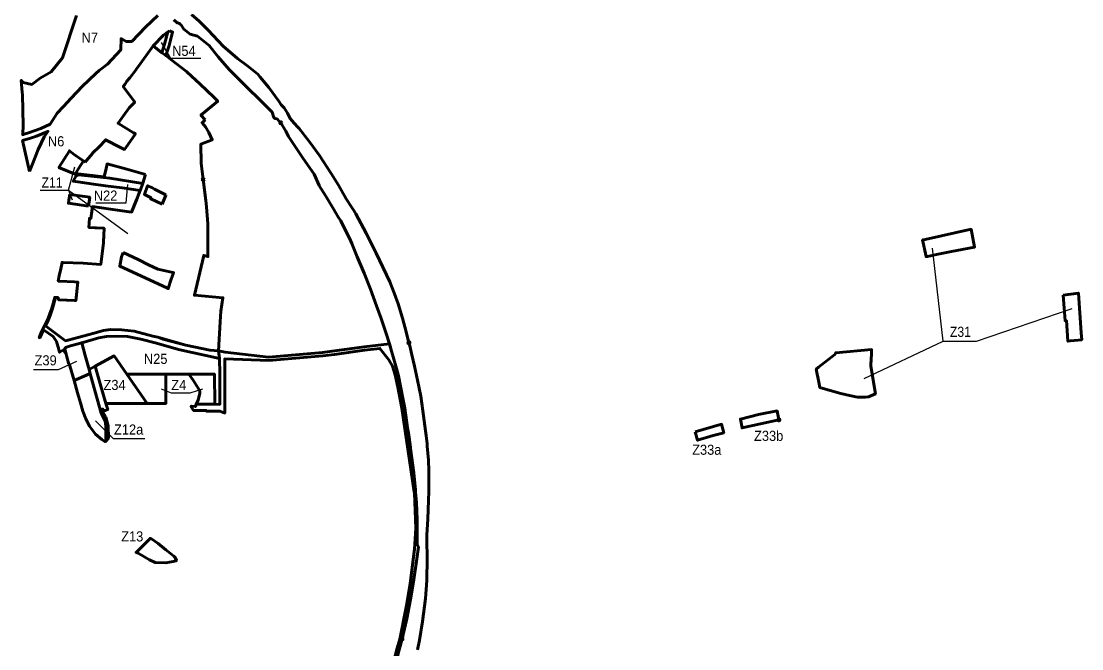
# Model space of a CAD drawing. Extents: x -650277 to -643420, y -1073980 to -1066720.
# Drawn here: x -645938 to -643420, y -1070698 to -1069207 of the extents above; entities that cross this region are included whole.
import ezdxf

# ---------------------------------------------------------------- set-up
doc = ezdxf.new("R2010")
doc.units = 0
doc.header["$LTSCALE"] = 9.6
doc.header["$PDMODE"] = 32
doc.header["$PDSIZE"] = 4.8
for name, color, linetype, lineweight in [('1', 7, 'Continuous', 60), ('11', 7, 'Continuous', 60), ('15', 7, 'Continuous', 60), ('3', 7, 'Continuous', 60), ('40', 7, 'Continuous', 60), ('42', 7, 'Continuous', 60), ('5', 7, 'Continuous', 60), ('60', 7, 'Continuous', 60), ('63', 7, 'Continuous', 25), ('7', 7, 'Continuous', 60), ('8', 7, 'Continuous', 60)]:
    doc.layers.add(name, color=color, linetype=linetype, lineweight=lineweight)

msp = doc.modelspace()

# ---------------------------------------------------------------- linework, layer by layer
at = {"layer": '1'}
for p, q in [((-645623.75, -1069825.97), (-645590.964, -1069841.09)), ((-645726.542, -1069939.398), (-645742.967, -1069941.862))]:
    msp.add_line(p, q, dxfattribs=at)
for points in [[(-645668.722, -1069398.75), (-645696.19, -1069362.01), (-645692.38, -1069356.67), (-645690.81, -1069354.28), (-645687.22, -1069349), (-645680.8, -1069341.08), (-645667, -1069324.06), (-645664.89, -1069320.2), (-645658.9, -1069312.83), (-645625.11, -1069265.42), (-645604.114, -1069281.49), (-645594.94, -1069288.511)], [(-645594.94, -1069288.511), (-645583.13, -1069297.55), (-645546.19, -1069325.81), (-645544.26, -1069327.35), (-645513.41, -1069356.18), (-645480.72, -1069386.96), (-645471.738, -1069397.026), (-645511.464, -1069429.794), (-645501.878, -1069440.838)], [(-645707.04, -1069449.546), (-645708.48, -1069448.63), (-645696.45, -1069432.21), (-645682.28, -1069412.88), (-645678.06, -1069408.54), (-645668.61, -1069398.9), (-645668.722, -1069398.75)], [(-645501.878, -1069440.838), (-645508.994, -1069447.955), (-645501, -1069458), (-645493, -1069471), (-645484.783, -1069488.256), (-645512, -1069499), (-645511, -1069544), (-645506, -1069583)], [(-645786.388, -1069541.673), (-645779.376, -1069532.962), (-645778.754, -1069532.198), (-645769.369, -1069520.672), (-645768.995, -1069520.305), (-645752.715, -1069504.328), (-645738.986, -1069489.868), (-645737.897, -1069488.534), (-645702.82, -1069506.64), (-645692.87, -1069511.229), (-645690.84, -1069508.32), (-645667.31, -1069474.6), (-645671.75, -1069471.99), (-645707.04, -1069449.546)], [(-645836.44, -1069534.5), (-645824.05, -1069514.34), (-645811.75, -1069523.81), (-645808.1, -1069526.61), (-645799.07, -1069532.8), (-645790.62, -1069538.59), (-645786.388, -1069541.673)], [(-645810.08, -1069570.39), (-645848.78, -1069553.91), (-645836.44, -1069534.5)], [(-645643.16, -1069570.6), (-645687.29, -1069558.04), (-645734.5, -1069545.89), (-645736.8, -1069556.91), (-645741.14, -1069576.19), (-645769.04, -1069573), (-645803.513, -1069569.263), (-645810.08, -1069570.39)], [(-645676.34, -1069660.28), (-645670.23, -1069644.67), (-645664.19, -1069629.24), (-645657.52, -1069612.2), (-645656.15, -1069608.71), (-645649.91, -1069592.39), (-645648.68, -1069589.06), (-645644.56, -1069575.61), (-645643.16, -1069570.6)], [(-645594.58, -1069619.56), (-645621.56, -1069605.68), (-645626.95, -1069602.91), (-645638.203, -1069597.8), (-645645.715, -1069618.085), (-645629.78, -1069626.03), (-645630.93, -1069628.84), (-645603.7, -1069641.75)], [(-645506, -1069583), (-645500.137, -1069632.833), (-645500.137, -1069632.833)], [(-645849.79, -1069868.4), (-645811.848, -1069870.577), (-645808.84, -1069870.75), (-645804.28, -1069826.76), (-645812.18, -1069826.3), (-645847.62, -1069824.26), (-645850.63, -1069824.09), (-645848.35, -1069812.09), (-645844.57, -1069795.07), (-645841.41, -1069779.76), (-645839.658, -1069779.835), (-645791.2, -1069781.92), (-645749.48, -1069784.61), (-645743.36, -1069733.7), (-645741.43, -1069698.68), (-645777.62, -1069696.85), (-645776.45, -1069675.26), (-645773.02, -1069675.47), (-645769.264, -1069647.213), (-645726.57, -1069653.22), (-645676.34, -1069660.28), (-645664.19, -1069629.24), (-645656.15, -1069608.71)], [(-645823.082, -1069618.279), (-645823.13, -1069618.452), (-645825.295, -1069632.053), (-645826.133, -1069638.843), (-645826.151, -1069639.057), (-645778.45, -1069645.92)], [(-645778.45, -1069645.92), (-645775.46, -1069625.13), (-645823.082, -1069618.279)], [(-645603.7, -1069641.75), (-645594.818, -1069620.139), (-645594.58, -1069619.56)], [(-645839.721, -1069780.247), (-645839.658, -1069779.835), (-645791.2, -1069781.92), (-645749.48, -1069784.61), (-645743.36, -1069733.7), (-645743.01, -1069730.72), (-645741.43, -1069698.68), (-645763.24, -1069697.58), (-645777.62, -1069696.85), (-645776.45, -1069675.26), (-645773.02, -1069675.47), (-645769.36, -1069648), (-645769.264, -1069647.213), (-645726.57, -1069653.22), (-645676.34, -1069660.28)], [(-645500.137, -1069632.833), (-645498, -1069648), (-645495, -1069688), (-645495, -1069744), (-645495, -1069766), (-645504.976, -1069763.332), (-645527, -1069858), (-645459.312, -1069864.01), (-645464.288, -1069895.362), (-645465.756, -1069921.035), (-645469.701, -1069990.011)], [(-645696.517, -1069756.039), (-645700.028, -1069766.286), (-645704.355, -1069788.786), (-645623.75, -1069825.97)], [(-645578.134, -1069803.73), (-645613.84, -1069795.78), (-645635.79, -1069785.23), (-645660.57, -1069773.31), (-645696.517, -1069756.039)], [(-645804.185, -1069825.84), (-645804.28, -1069826.76), (-645812.18, -1069826.3), (-645847.62, -1069824.26), (-645850.63, -1069824.09), (-645848.35, -1069812.09), (-645844.57, -1069795.07), (-645841.41, -1069779.76), (-645839.658, -1069779.835), (-645839.721, -1069780.247)], [(-645742.967, -1069941.862), (-645768.424, -1069948.431), (-645833, -1069966), (-645880.431, -1069930.3), (-645874.219, -1069917.496), (-645869.262, -1069905.935), (-645863.95, -1069889.468), (-645857.289, -1069863.338), (-645857.204, -1069862.954), (-645850.92, -1069863.41), (-645849.79, -1069868.4), (-645808.84, -1069870.75), (-645808.28, -1069865.39), (-645804.185, -1069825.84)], [(-645590.964, -1069841.09), (-645589.23, -1069841.89), (-645582.31, -1069820.05), (-645577.52, -1069807.26), (-645576.34, -1069804.13), (-645578.134, -1069803.73)], [(-645469.701, -1069990.011), (-645490.814, -1069988.074), (-645547.4, -1069976.382), (-645614.072, -1069957.797), (-645625.979, -1069954.92), (-645670.325, -1069943.002), (-645699.889, -1069939.714), (-645726.542, -1069939.398)], [(-645772.853, -1070049.868), (-645774.423, -1070044.167), (-645783.063, -1070047.855), (-645812.76, -1070060.53)], [(-645737.756, -1070204.389), (-645737.624, -1070169.544), (-645738.79, -1070156.281), (-645748.62, -1070137.889), (-645772.853, -1070049.868)], [(-645812.76, -1070060.53), (-645804.52, -1070089.63), (-645797.66, -1070113.88), (-645791.72, -1070133.09), (-645784.83, -1070151.9), (-645784.83, -1070151.9)], [(-645784.83, -1070151.9), (-645776.26, -1070168.94), (-645761.78, -1070188.29), (-645746.73, -1070201.04), (-645739.12, -1070205.9), (-645737.756, -1070204.389)]]:
    msp.add_lwpolyline(points, dxfattribs=at)
for points in [[(-645836.44, -1069534.5), (-645848.78, -1069553.91), (-645810.08, -1069570.39), (-645803.07, -1069558.62), (-645790.62, -1069538.59), (-645799.07, -1069532.8), (-645808.1, -1069526.61), (-645811.75, -1069523.81), (-645824.05, -1069514.34)], [(-645639.638, -1070114.895), (-645594.733, -1070114.868), (-645595.2, -1070045.403), (-645687.31, -1070045.724)], [(-645522.587, -1070116.952), (-645478.664, -1070117.114), (-645479.429, -1070045.409), (-645540.433, -1070045.752), (-645530.3, -1070060.08), (-645514.49, -1070085.4), (-645514.56, -1070090.91), (-645514.61, -1070094.35), (-645517.02, -1070103.08), (-645518.35, -1070106.87), (-645521.73, -1070114.83)], [(-645594.769, -1070494.065), (-645577.47, -1070490.3), (-645571.13, -1070488.89), (-645569.97, -1070488.3), (-645572.86, -1070481.41), (-645575.7, -1070477.77), (-645591.49, -1070465.19), (-645594.62, -1070462.7), (-645612.77, -1070447.82), (-645631.63, -1070435.3), (-645636.42, -1070439.93), (-645648.9, -1070452.38), (-645665.6, -1070469.04), (-645660.29, -1070471.12), (-645643.4, -1070481.02), (-645633.35, -1070486.91), (-645620.22, -1070493)]]:
    msp.add_lwpolyline(points, close=True, dxfattribs=at)
msp.add_point((-645506, -1069583), dxfattribs=at)
at = {"layer": '11'}
msp.add_lwpolyline([(-645639.638, -1070114.895), (-645687.31, -1070045.724), (-645717.36, -1070002.12), (-645762.868, -1070026.606), (-645757.215, -1070045.97), (-645737.075, -1070114.955)], close=True, dxfattribs=at)
at = {"layer": '15'}
for points in [[(-645586.39, -1069229.32), (-645589.844, -1069231.908), (-645597.738, -1069261.522), (-645604.114, -1069281.49), (-645594.94, -1069288.511), (-645587.298, -1069264.578), (-645578.713, -1069232.375)], [(-645735.532, -1069956.306), (-645712.222, -1069954.725), (-645686.147, -1069956.306), (-645654.145, -1069962.232), (-645617.403, -1069971.714), (-645565.133, -1069986.508), (-645467.472, -1070008.38), (-645469.701, -1069990.011), (-645490.814, -1069988.074), (-645547.4, -1069976.382), (-645601.753, -1069962.317), (-645614.072, -1069957.797), (-645625.979, -1069954.92), (-645670.325, -1069943.002), (-645699.889, -1069939.714), (-645726.542, -1069939.398), (-645742.967, -1069941.862), (-645768.424, -1069948.431), (-645806, -1069959), (-645833, -1069966), (-645880.431, -1069930.3), (-645874.219, -1069917.496), (-645869.262, -1069905.935), (-645863.95, -1069889.468), (-645857.289, -1069863.338), (-645857.204, -1069862.954), (-645858.78, -1069862.84), (-645865.78, -1069888.76), (-645870.89, -1069903.5), (-645876.15, -1069916.47), (-645892.09, -1069947.98), (-645895.66, -1069958.42), (-645894.25, -1069958.7), (-645885.422, -1069940.184), (-645862.782, -1069955.809), (-645854.81, -1069967.927), (-645849.1, -1069986.42), (-645847.135, -1069993.337), (-645836.64, -1069987.18), (-645834.65, -1069994.21), (-645833.32, -1069991.86), (-645835, -1069985), (-645833, -1069982), (-645821, -1069978), (-645794.679, -1069970.596), (-645753.706, -1069959.071)]]:
    msp.add_lwpolyline(points, close=True, dxfattribs=at)
for points in [[(-645061.76, -1069981.21), (-645064.052, -1069973.429), (-645124.233, -1069980.695), (-645222.809, -1069993.701), (-645350.784, -1070005.227), (-645453.852, -1069992.968), (-645469.701, -1069990.011), (-645467.472, -1070008.38), (-645467.068, -1070044.959), (-645466.96, -1070117.157), (-645478.664, -1070117.114), (-645522.587, -1070116.952), (-645524.82, -1070122.48), (-645534.63, -1070121.09), (-645534.7, -1070122.95), (-645529.17, -1070131.4), (-645499.276, -1070131.652), (-645499.142, -1070133.293), (-645466.862, -1070133.219), (-645454.881, -1070137.836), (-645455.073, -1070009.111), (-645350.591, -1070013.242), (-645221.99, -1070001.66), (-645194.003, -1069998.417), (-645123.206, -1069988.629), (-645086.484, -1069984.195), (-645065.235, -1070011.695)], [(-645033.53, -1070674.55), (-645022.64, -1070626.93), (-645014.07, -1070580.72), (-645006.44, -1070538.78), (-644998.92, -1070484.58), (-644995.14, -1070455.72), (-644998.17, -1070450.59), (-644998.25, -1070430.5), (-644997.87, -1070391.16), (-644999.47, -1070349.63), (-645001.64, -1070326.4), (-645001.81, -1070324.58), (-645002.308, -1070319.268), (-645005.98, -1070280.14), (-645013.51, -1070222.04), (-645013.77, -1070220.04), (-645016.92, -1070196.32), (-645018.56, -1070184.92), (-645021.14, -1070173.07), (-645027.49, -1070126.56), (-645032.21, -1070102.73), (-645042.27, -1070049.23), (-645047.28, -1070031.83), (-645054.73, -1070004.56), (-645060.612, -1069985.022), (-645061.76, -1069981.21)], [(-645757.215, -1070045.97), (-645762.868, -1070026.606), (-645777.143, -1070034.287), (-645772.853, -1070049.868), (-645748.62, -1070137.889)], [(-645065.235, -1070011.695), (-645056.555, -1070026.163), (-645050.293, -1070047.035), (-645043.92, -1070076.344), (-645034.122, -1070126.616), (-645004.791, -1070324.889), (-645004.523, -1070326.697)], [(-645737.63, -1070147.39), (-645747.67, -1070129.14), (-645745.29, -1070127.83), (-645744.73, -1070129), (-645743.87, -1070130.15), (-645742.67, -1070131.07), (-645741.83, -1070131.53), (-645740.89, -1070131.8), (-645739.41, -1070131.93), (-645738.41, -1070131.78), (-645737.48, -1070131.45), (-645734.77, -1070130.18), (-645732.91, -1070129.5), (-645737.075, -1070114.955), (-645757.215, -1070045.97)], [(-645748.62, -1070137.889), (-645738.79, -1070156.281), (-645737.624, -1070169.544), (-645737.756, -1070204.389)], [(-645737.756, -1070204.389), (-645731.3, -1070197.24), (-645731.94, -1070167.87), (-645737.63, -1070147.39)], [(-645004.523, -1070326.697), (-645004.434, -1070327.302), (-645001.312, -1070412.099), (-645004.327, -1070461.264), (-645014.277, -1070543.11), (-645023.048, -1070595.033), (-645039.574, -1070675.065)], [(-645039.574, -1070675.065), (-645045.493, -1070696.321), (-645059.308, -1070747.712), (-645059.403, -1070749.195), (-645053.21, -1070749.75), (-645052.4, -1070746.427), (-645046.63, -1070722.77), (-645041, -1070700.44), (-645033.53, -1070674.55)]]:
    msp.add_lwpolyline(points, dxfattribs=at)
msp.add_point((-645033.53, -1070674.55), dxfattribs=at)
at = {"layer": '3'}
for points in [[(-643791.88, -1069725.25), (-643797.75, -1069726.51), (-643789.3, -1069766.05), (-643786.35, -1069765.46), (-643764.94, -1069761.27), (-643729.34, -1069754.3), (-643674.3, -1069743.53), (-643682.61, -1069701.16)], [(-643463.51, -1069857.44), (-643459.13, -1069918.47), (-643456.14, -1069918.26), (-643452.63, -1069967.09), (-643446.63, -1069966), (-643419.62, -1069963.66), (-643420.79, -1069947.35), (-643427.6, -1069852.59)], [(-643920.84, -1070026.46), (-643920.29, -1070017.73), (-643920.16, -1070015.69), (-643918.69, -1069992.23), (-643918.88, -1069986.82), (-644004.06, -1069994.59), (-644005.92, -1069998.62), (-644044.7, -1070029.04), (-644050.12, -1070033.64), (-644044.18, -1070064.43), (-644041.71, -1070077.29), (-644022.77, -1070082.66), (-643991.99, -1070091.37), (-643971.03, -1070095.79), (-643951.99, -1070100.35), (-643933.96, -1070100.18), (-643926.33, -1070099.5), (-643909.87, -1070091.95)]]:
    msp.add_lwpolyline(points, close=True, dxfattribs=at)
for points in [[(-645794.679, -1069970.596), (-645821, -1069978), (-645833, -1069982), (-645835, -1069985), (-645833.32, -1069991.86)], [(-645777.143, -1070034.287), (-645786.238, -1070001.251), (-645794.679, -1069970.596)], [(-645833.32, -1069991.86), (-645828.9, -1070007.76), (-645825.08, -1070021.52)], [(-645825.08, -1070021.52), (-645823.76, -1070021.67), (-645822.549, -1070025.948), (-645812.76, -1070060.53), (-645783.063, -1070047.855), (-645774.423, -1070044.167), (-645777.143, -1070034.287)]]:
    msp.add_lwpolyline(points, dxfattribs=at)
at = {"layer": '40'}
for points in [[(-645698.83, -1069602.85), (-645656.15, -1069608.71), (-645649.91, -1069592.39), (-645727.71, -1069579.61), (-645803.33, -1069571.62), (-645808.18, -1069573.7), (-645814.82, -1069586.81), (-645777.26, -1069592.07), (-645772.58, -1069592.73), (-645738.13, -1069597.46)], [(-645595.2, -1070045.403), (-645479.429, -1070045.409), (-645478.664, -1070117.114), (-645466.96, -1070117.157), (-645467.068, -1070044.959), (-645467.472, -1070008.38), (-645565.133, -1069986.508), (-645617.403, -1069971.714), (-645654.145, -1069962.232), (-645686.147, -1069956.306), (-645712.222, -1069954.725), (-645735.532, -1069956.306), (-645753.706, -1069959.071), (-645794.679, -1069970.596), (-645786.238, -1070001.251), (-645777.143, -1070034.287), (-645762.868, -1070026.606), (-645717.36, -1070002.12), (-645687.31, -1070045.724)]]:
    msp.add_lwpolyline(points, close=True, dxfattribs=at)
at = {"layer": '42'}
msp.add_lwpolyline([(-645604.114, -1069281.49), (-645597.738, -1069261.522), (-645589.844, -1069231.908), (-645600.55, -1069239.93), (-645625.11, -1069265.42)], close=True, dxfattribs=at)
at = {"layer": '5'}
msp.add_lwpolyline([(-644338.06, -1070182.64), (-644331.9, -1070202.4), (-644295.01, -1070190.9), (-644269.84, -1070184.57), (-644275.05, -1070164.59)], close=True, dxfattribs=at)
at = {"layer": '60'}
for points in [[(-645017.46, -1069970.61), (-645018.28, -1069967.49), (-645024.45, -1069944.43), (-645032.85, -1069912.07), (-645043.5, -1069878.37), (-645051.78, -1069854.2), (-645063.26, -1069825.99), (-645095.1, -1069757.62), (-645118.98, -1069710.08), (-645143.56, -1069664.05), (-645148.8, -1069656.1), (-645150.3, -1069653.84), (-645153.33, -1069649.24), (-645166.67, -1069629), (-645184.88, -1069596.58), (-645202.56, -1069568.23), (-645230.1, -1069525.98), (-645253.4, -1069493.06), (-645278.31, -1069461.33), (-645281.4, -1069458.4), (-645290.5, -1069449.03), (-645299.61, -1069437.97), (-645306.16, -1069425.55), (-645314.14, -1069412.54), (-645321.1, -1069405.21), (-645326.59, -1069396.64), (-645350.63, -1069363.98), (-645371.12, -1069339.47), (-645376.38, -1069332.65), (-645400.07, -1069313.32), (-645424.8, -1069295.24), (-645458.45, -1069265.56), (-645494.13, -1069227.63), (-645515.89, -1069206.66), (-645534.25, -1069190.56)], [(-645575.58, -1069203.57), (-645568.9, -1069209.87), (-645567.07, -1069210.45), (-645562.17, -1069212.02), (-645560.72, -1069214.25), (-645559.33, -1069214.54), (-645552.2, -1069225.59), (-645537.44, -1069237.41), (-645519.59, -1069242.38), (-645491.63, -1069264.25), (-645470.44, -1069291.24), (-645444.62, -1069321.35), (-645405.7, -1069360.27), (-645368.13, -1069397.37), (-645358.04, -1069406.84), (-645342.49, -1069423.06), (-645339.31, -1069433.27), (-645336.66, -1069437.47), (-645330.57, -1069438.89), (-645327.2, -1069442.53), (-645323.36, -1069445.79), (-645322.13, -1069447.96)], [(-645322.13, -1069447.96), (-645309.62, -1069467.79), (-645303.57, -1069480.49), (-645268.57, -1069533.23), (-645242.75, -1069570.26), (-645230.42, -1069597.39), (-645227.27, -1069602.68), (-645225.7, -1069605.32), (-645214.76, -1069622.37), (-645198.41, -1069650.49), (-645185.17, -1069673.38), (-645179.12, -1069681.3), (-645170.3, -1069698.91), (-645158.43, -1069722.61), (-645153.44, -1069734.71), (-645140.27, -1069766.68), (-645123.84, -1069805.38), (-645108.74, -1069843.58), (-645094.42, -1069882.65), (-645083.31, -1069913.37), (-645071.53, -1069948.89), (-645063.96, -1069973.73), (-645063.23, -1069976.2), (-645062.57, -1069978.46)], [(-644996.88, -1070059.73), (-645004.02, -1070026.44), (-645010.54, -1069999.3), (-645015.548, -1069978.177), (-645016.01, -1069976.23), (-645016.89, -1069972.82), (-645017.46, -1069970.61)], [(-645062.57, -1069978.46), (-645061.76, -1069981.21), (-645060.612, -1069985.022), (-645054.73, -1070004.56), (-645047.28, -1070031.83), (-645042.27, -1070049.23), (-645032.21, -1070102.73), (-645027.49, -1070126.56), (-645021.14, -1070173.07), (-645018.56, -1070184.92), (-645016.92, -1070196.32), (-645013.77, -1070220.04), (-645013.51, -1070222.04), (-645005.98, -1070280.14), (-645002.308, -1070319.268), (-645001.81, -1070324.58), (-645001.64, -1070326.4), (-644999.47, -1070349.63), (-644997.87, -1070391.16), (-644998.25, -1070430.5), (-644998.17, -1070450.59), (-644995.14, -1070455.72), (-644998.92, -1070484.58), (-645006.44, -1070538.78), (-645014.07, -1070580.72), (-645022.64, -1070626.93), (-645033.53, -1070674.55)], [(-644997.14, -1070700.88), (-644992.6, -1070677.92), (-644985.04, -1070633.43), (-644978.44, -1070578.56), (-644975.05, -1070536.16), (-644974.44, -1070482.48), (-644975.29, -1070440.14), (-644974.69, -1070427.86), (-644972.48, -1070389.15), (-644971.37, -1070345.98), (-644970.61, -1070323.44), (-644970.55, -1070321.56), (-644970.524, -1070315.358), (-644970.36, -1070275.49), (-644971.47, -1070250.14), (-644974, -1070216.2), (-644974.29, -1070213.17), (-644974.49, -1070210.98), (-644976.94, -1070191.41), (-644978.49, -1070180.05), (-644979.57, -1070167.9), (-644984.21, -1070132.81), (-644989.62, -1070097.79), (-644996.88, -1070059.73)], [(-645033.53, -1070674.55), (-645041, -1070700.44)]]:
    msp.add_lwpolyline(points, dxfattribs=at)
for p in [(-645322.13, -1069447.96), (-645017.46, -1069970.61), (-645033.53, -1070674.55)]:
    msp.add_point(p, dxfattribs=at)
at = {"layer": '63'}
for p, q in [((-645826, -1069608), (-645817, -1069631)), ((-645826, -1069608), (-645685, -1069711)), ((-643749.085, -1069967.17), (-643774.294, -1069746.101))]:
    msp.add_line(p, q, dxfattribs=at)
for points in [[(-645512, -1069295), (-645583, -1069295), (-645605, -1069257)], [(-645893, -1069608), (-645826, -1069608), (-645811, -1069553)], [(-645761, -1069638), (-645689, -1069638), (-645685, -1069595)], [(-643936.672, -1070055.449), (-643749.085, -1069967.17), (-643669.749, -1069967.17), (-643442.122, -1069889.276)], [(-645909, -1070034), (-645850, -1070034), (-645806.657, -1070014.297)], [(-645606, -1070080), (-645582, -1070090), (-645537, -1070090), (-645507, -1070080)], [(-645762, -1070156), (-645720, -1070198), (-645645, -1070198)]]:
    msp.add_lwpolyline(points, dxfattribs=at)
at = {"layer": '7'}
msp.add_line((-645918.82, -1069563.81), (-645910.9, -1069543.64), dxfattribs=at)
for points in [[(-645806.806, -1069193.112), (-645840.644, -1069294.052), (-645867.026, -1069327.317), (-645893.291, -1069341.938), (-645913.23, -1069356.892), (-645933.792, -1069352.53), (-645938.399, -1069347.452), (-645936.046, -1069375.651), (-645935.58, -1069381.24), (-645933.97, -1069453.52), (-645934.8, -1069474.71), (-645935.05, -1069476.32), (-645928.99, -1069474.55), (-645921.13, -1069472.25), (-645892.03, -1069461.43), (-645869.91, -1069451.02), (-645853.28, -1069425.27), (-645838.17, -1069409.28), (-645819.62, -1069389.66), (-645793.63, -1069362.15), (-645761.411, -1069331.17), (-645753.58, -1069323.64), (-645733.1, -1069308.58), (-645701.62, -1069274.36), (-645701.33, -1069247.86), (-645689, -1069254.5), (-645675.82, -1069254.48), (-645643.34, -1069220.59), (-645613.9, -1069193.45)], [(-645910.9, -1069543.64), (-645897.92, -1069511.49), (-645884.01, -1069481.56), (-645875.02, -1069468.52), (-645902.19, -1069480.13), (-645916.13, -1069484.55), (-645934.97, -1069490.31), (-645918.82, -1069563.81)]]:
    msp.add_lwpolyline(points, dxfattribs=at)
at = {"layer": '8'}
for p, q in [((-644138.78, -1070154.07), (-644143.31, -1070132.95)), ((-644182.31, -1070163.66), (-644138.78, -1070154.07))]:
    msp.add_line(p, q, dxfattribs=at)
msp.add_lwpolyline([(-644143.31, -1070132.95), (-644143.31, -1070132.95), (-644143.31, -1070132.95), (-644187.11, -1070141.58), (-644230.4, -1070152.08), (-644226.23, -1070173.28), (-644182.31, -1070163.66)], dxfattribs=at)
msp.add_point((-644138.78, -1070154.07), dxfattribs=at)

# ---------------------------------------------------------------- texts
at = {"layer": '63'}
for s, width, p in [('N7', 0.95, (-645795, -1069258)), ('N54', 0.95, (-645580, -1069289)), ('N6', 0.95, (-645875, -1069504)), ('Z11', 0.9, (-645890, -1069602)), ('N22', 0.95, (-645766, -1069633)), ('Z31', 0.9, (-643732.773, -1069956.784)), ('Z39', 0.95, (-645906.58, -1070024.53)), ('N25', 0.95, (-645647, -1070021)), ('Z34', 0.95, (-645743, -1070083)), ('Z4', 0.95, (-645582, -1070083)), ('Z12a', 0.95, (-645718, -1070189)), ('Z33b', 0.95, (-644198, -1070204)), ('Z33a', 0.95, (-644345, -1070237)), ('Z13', 0.95, (-645701, -1070443))]:
    msp.add_text(s, height=24, dxfattribs=dict(at, width=width)).set_placement(p)

doc.saveas('drawing.dxf')
